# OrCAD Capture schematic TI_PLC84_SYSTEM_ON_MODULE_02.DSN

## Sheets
1 Title / Notes
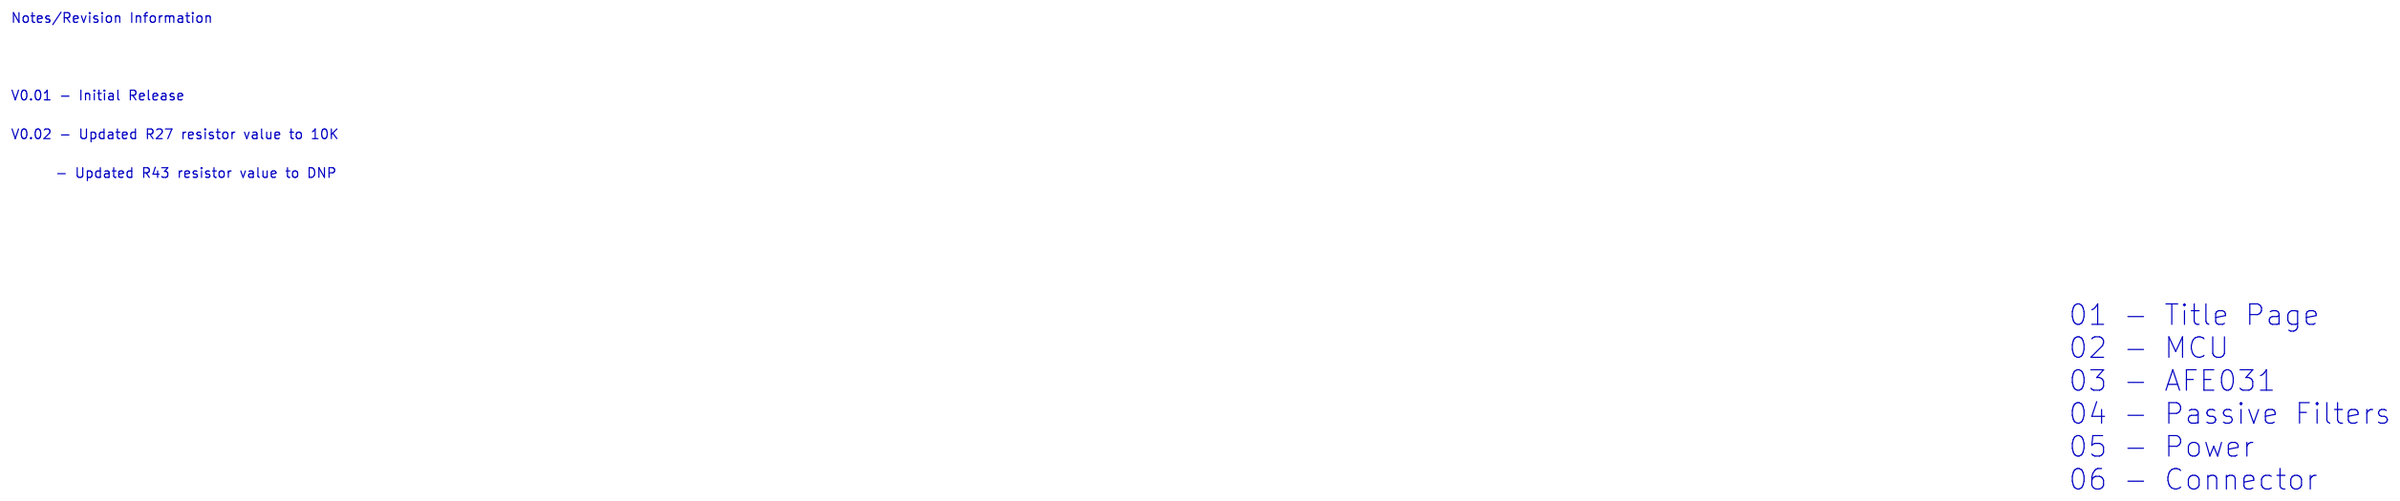
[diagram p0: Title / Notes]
2 MCU: size B; title: TIDM-SOMPLC-F28PLC84 MODULE; rev: 0.18; company: TI
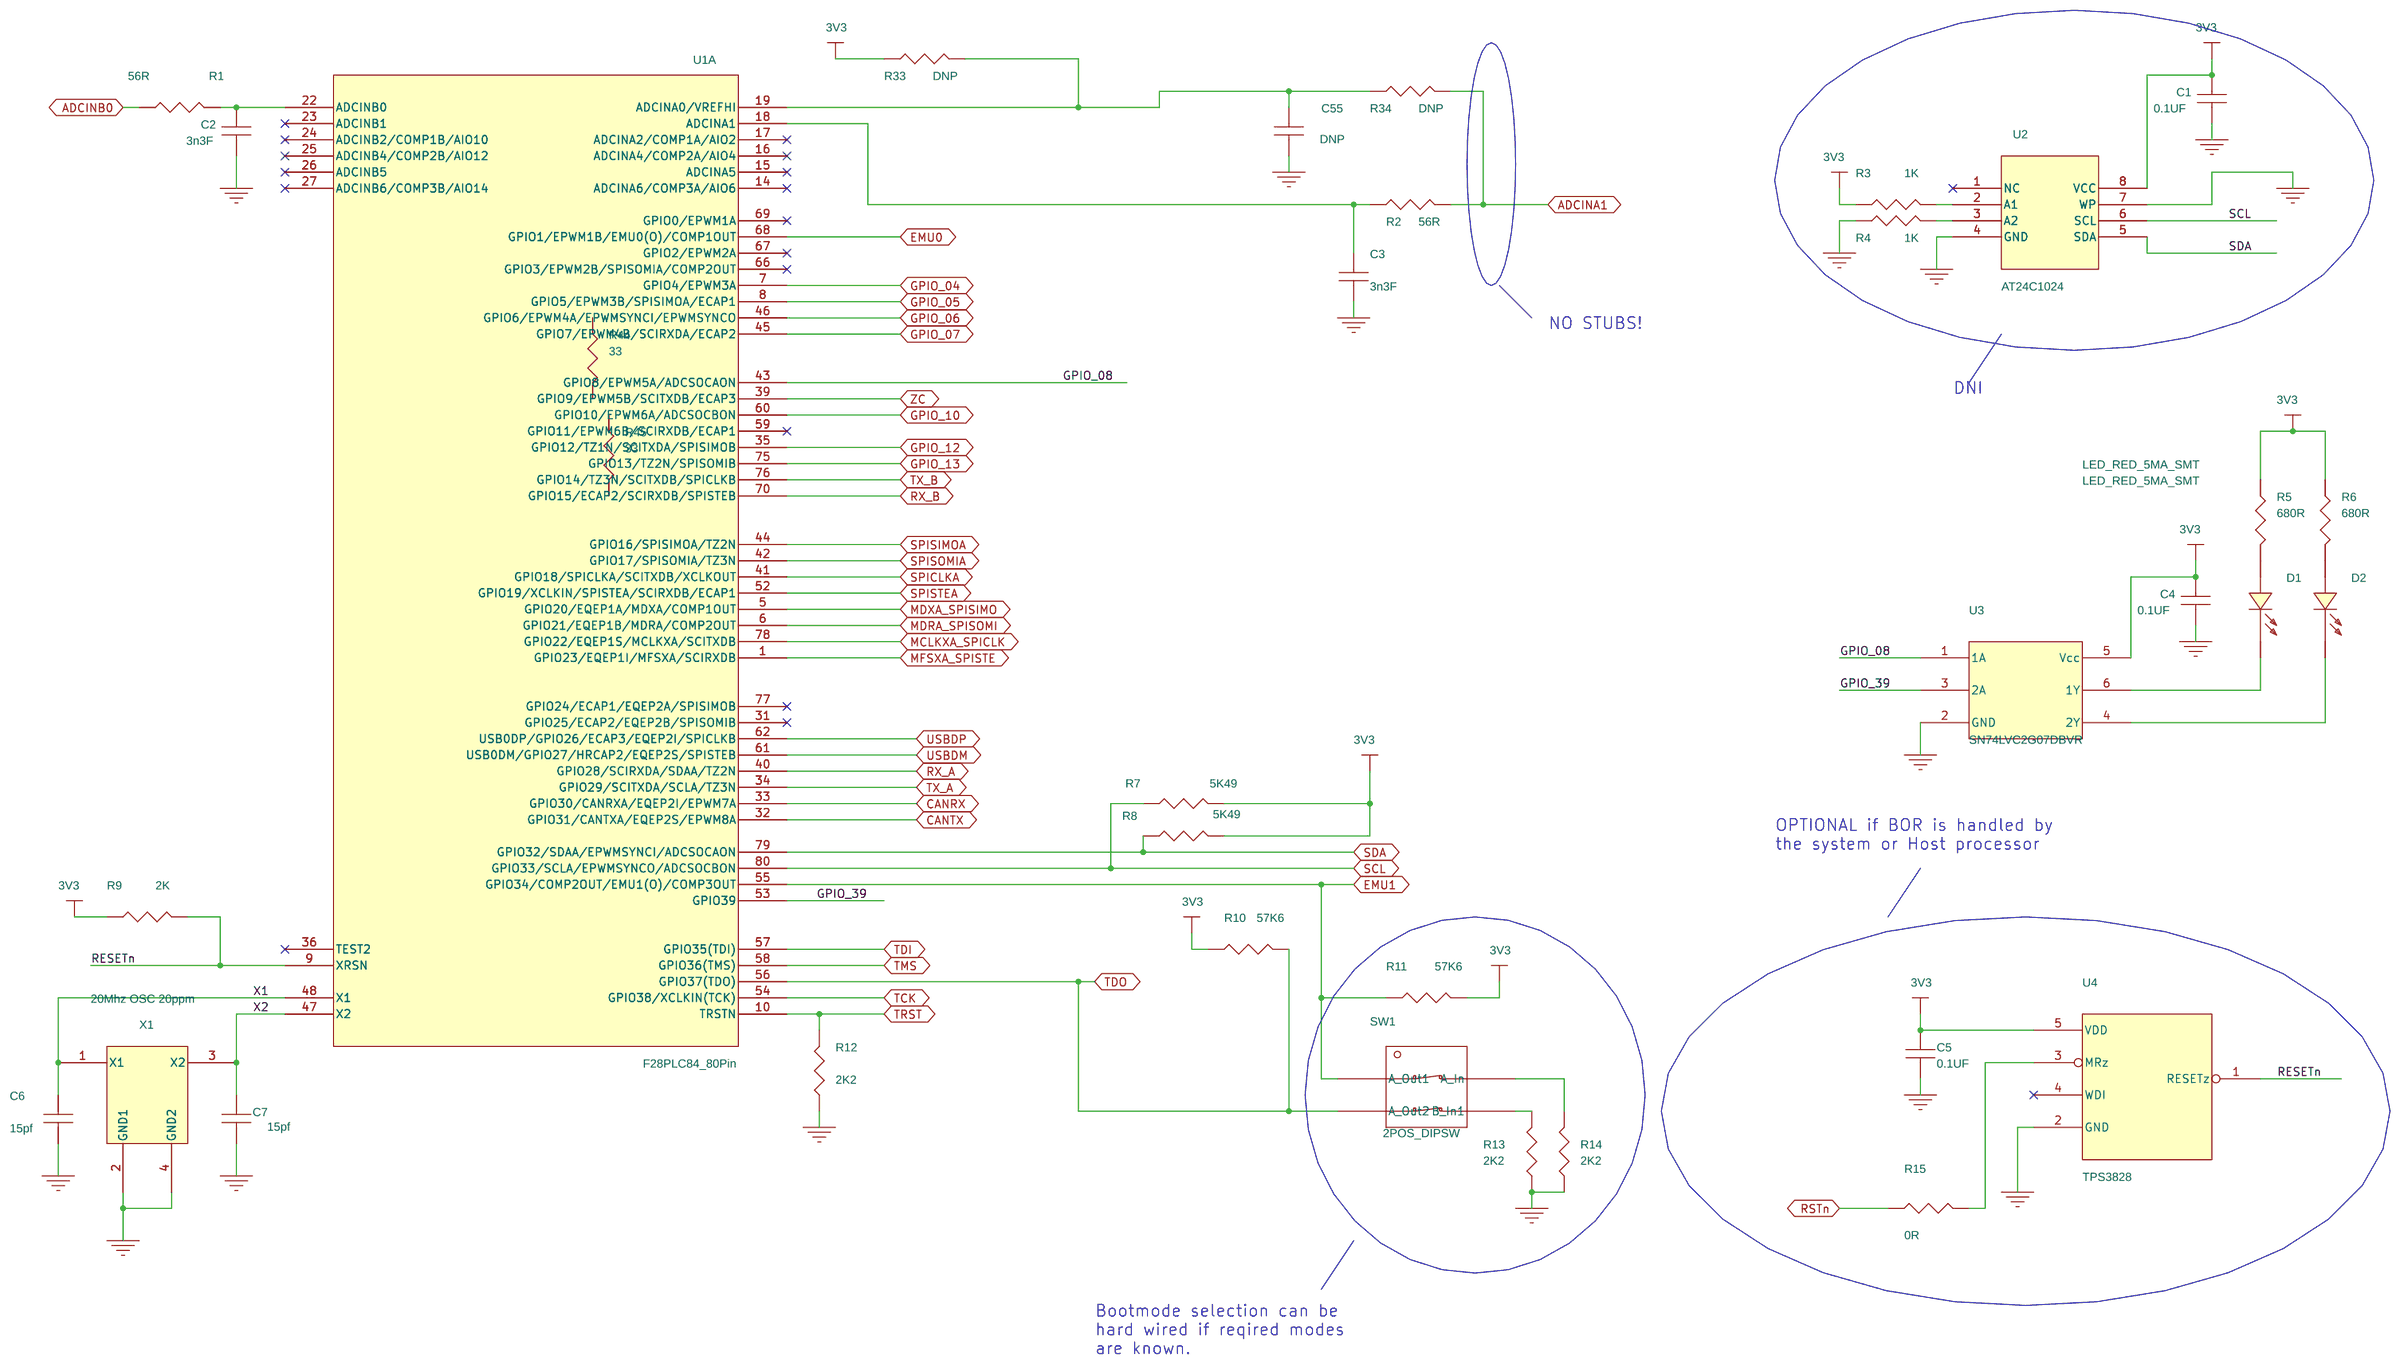
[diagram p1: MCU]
3 AFE031: size B; title: TIDM-SOMPLC-F28PLC84 MODULE; rev: 0.18; company: TI
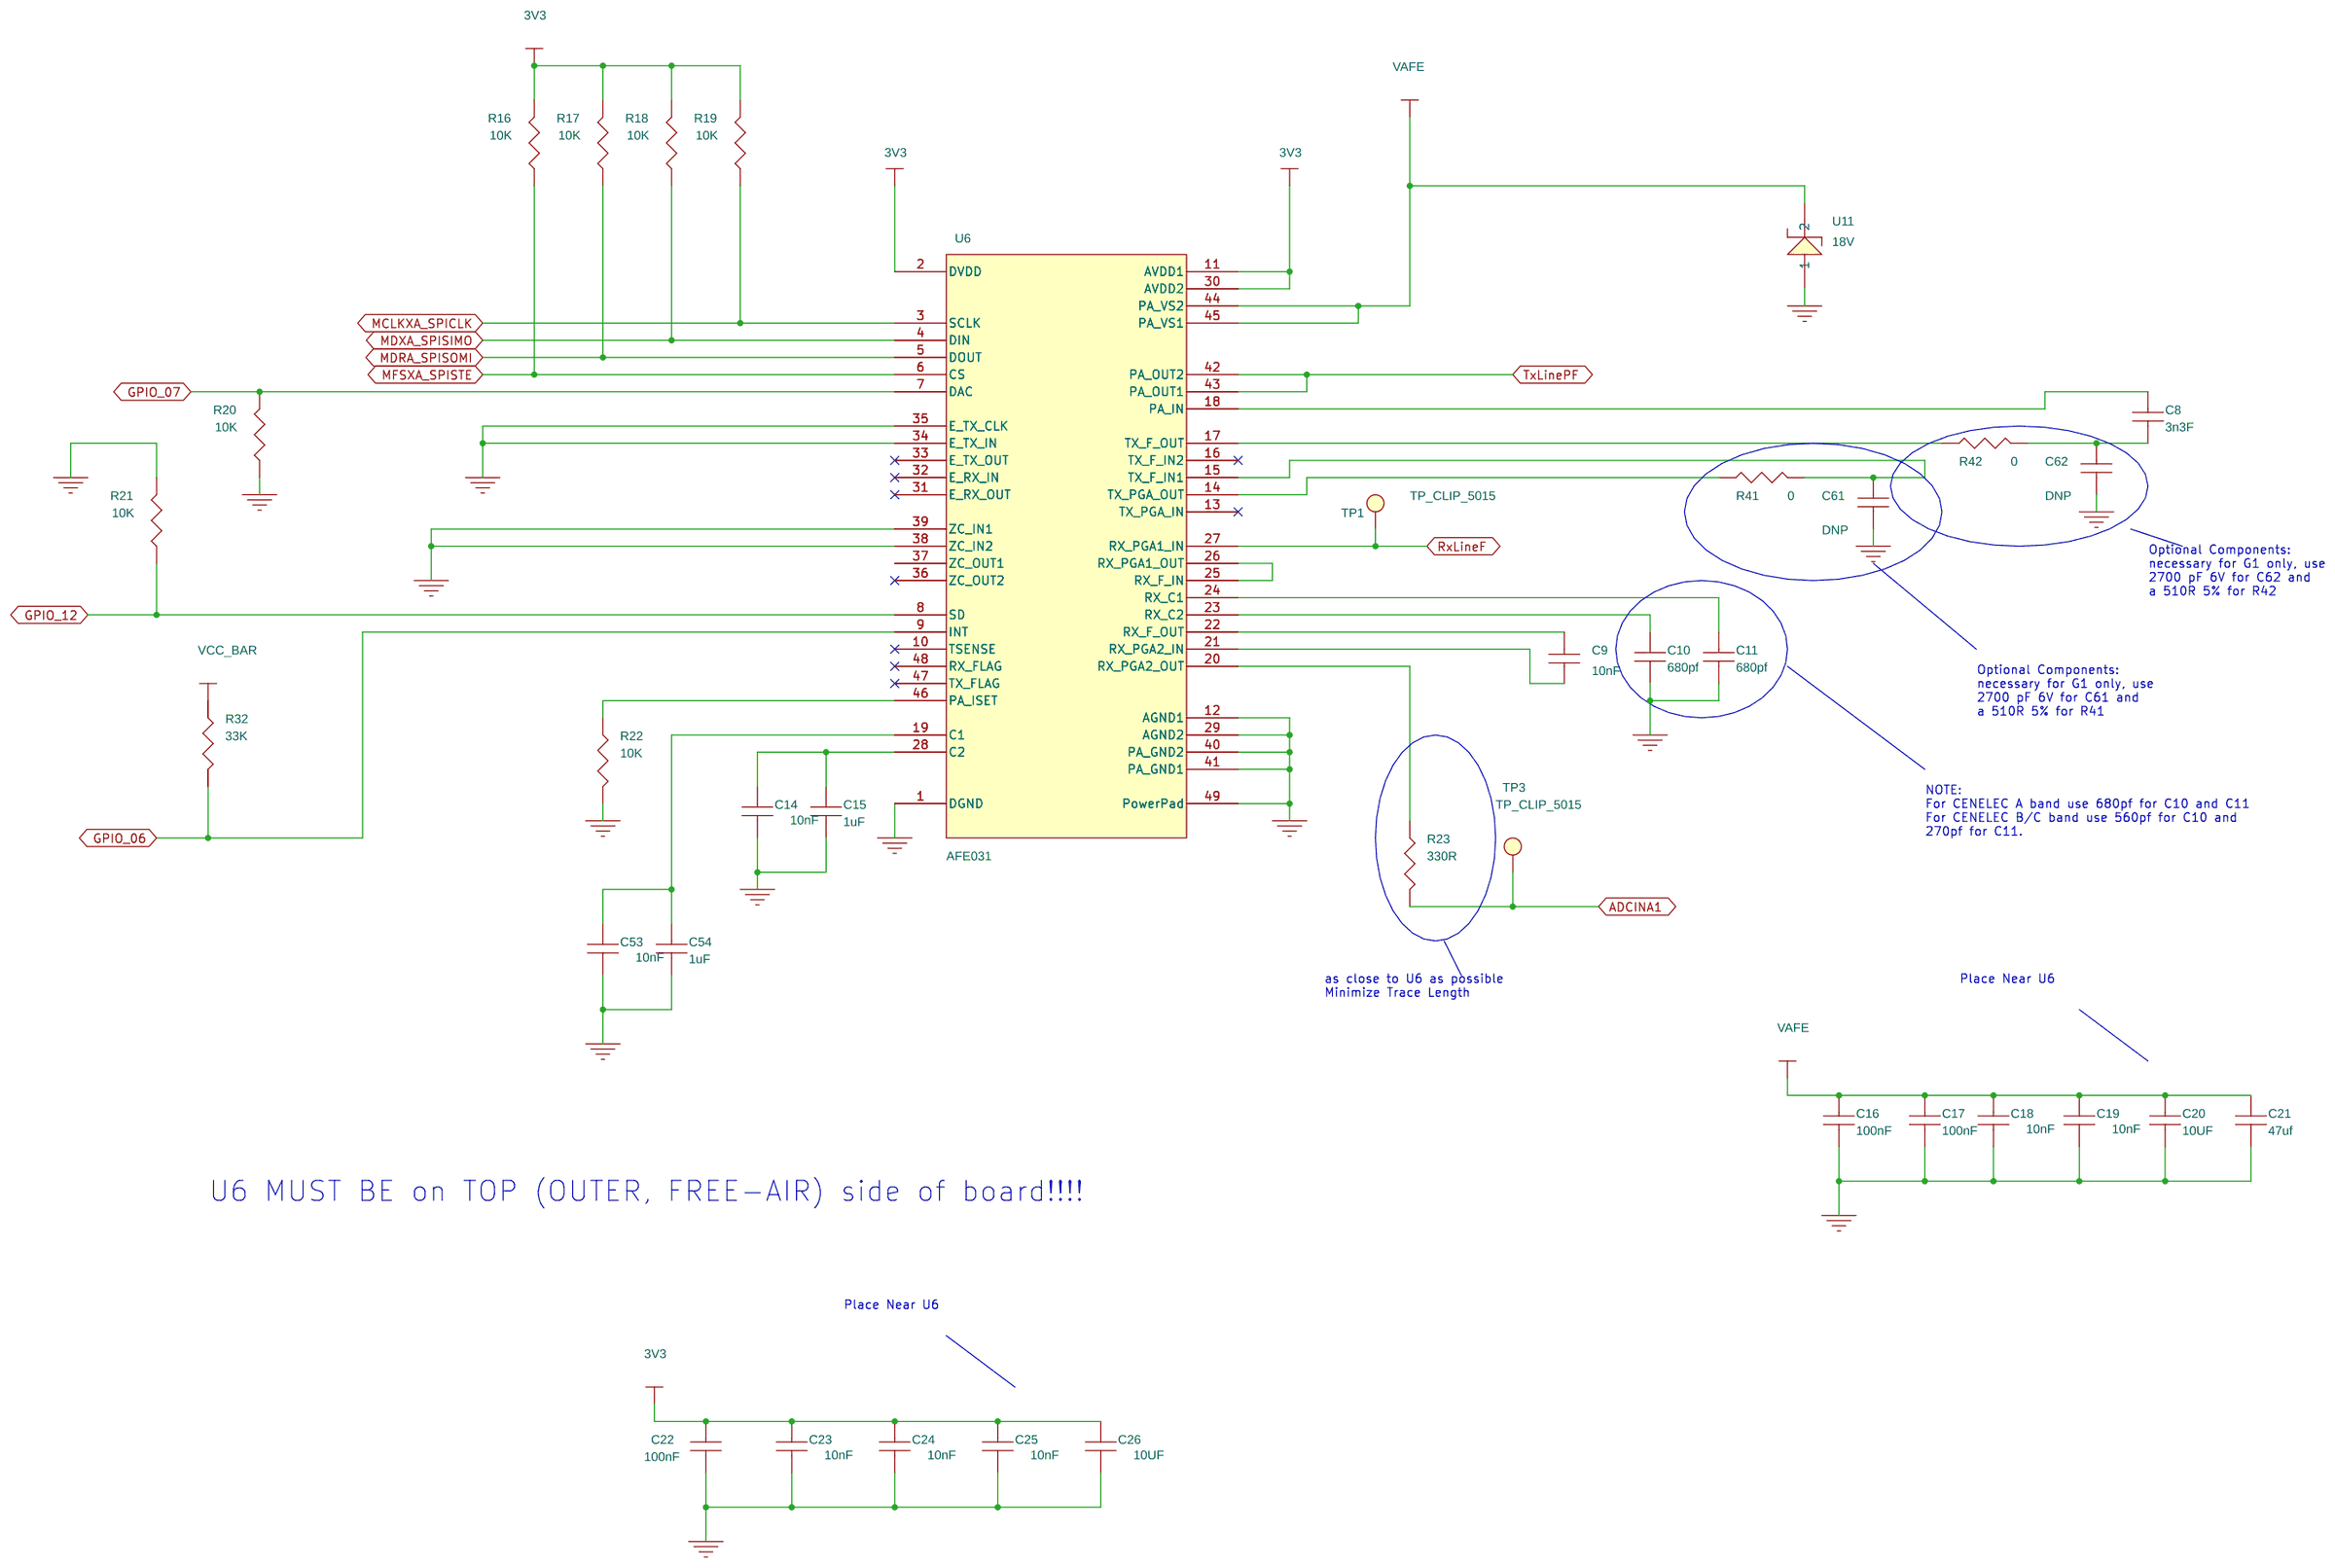
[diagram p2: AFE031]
4 Passive Filter: size B; title: TIDM-SOMPLC-F28PLC84 MODULE; rev: 0.18; company: TI
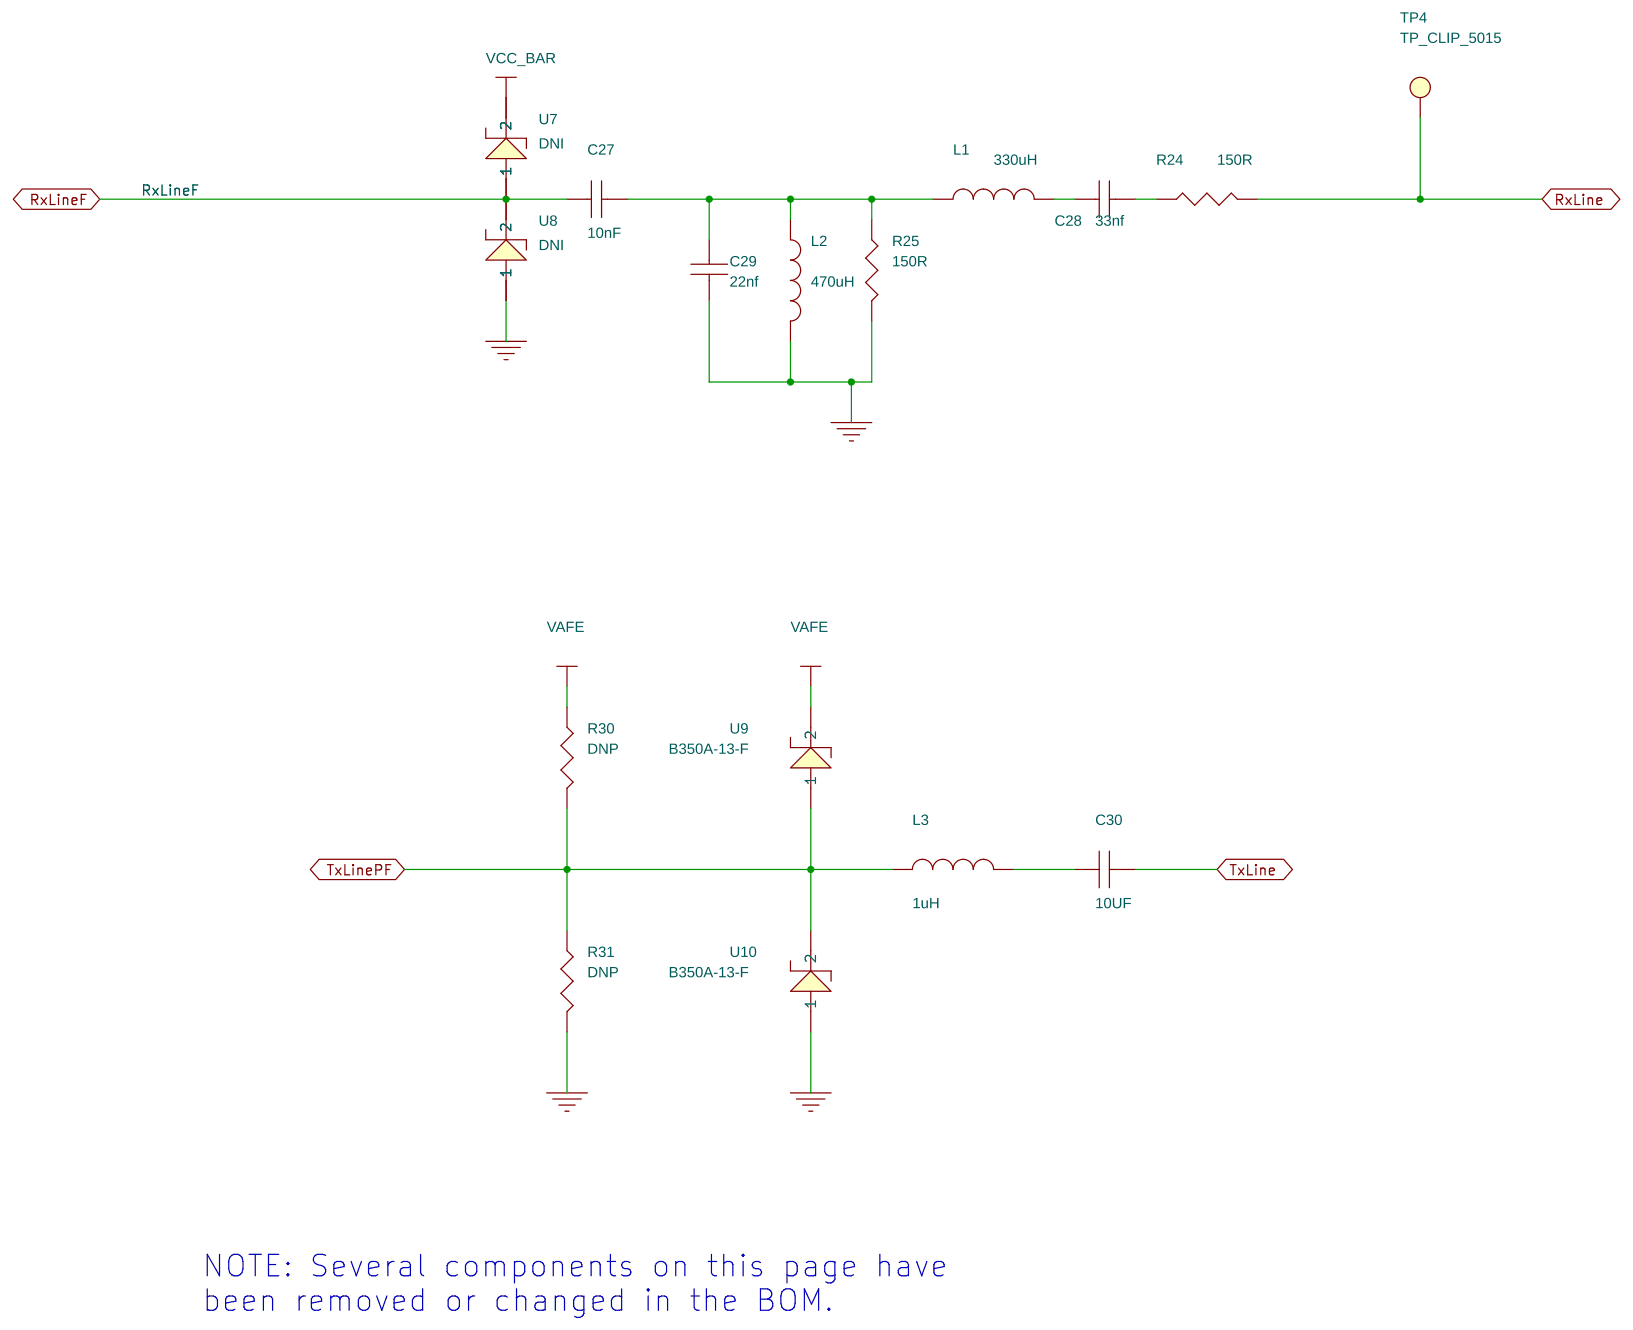
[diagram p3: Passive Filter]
5 Power: size B; title: TIDM-SOMPLC-F28PLC84 MODULE; rev: 0.18; company: TI
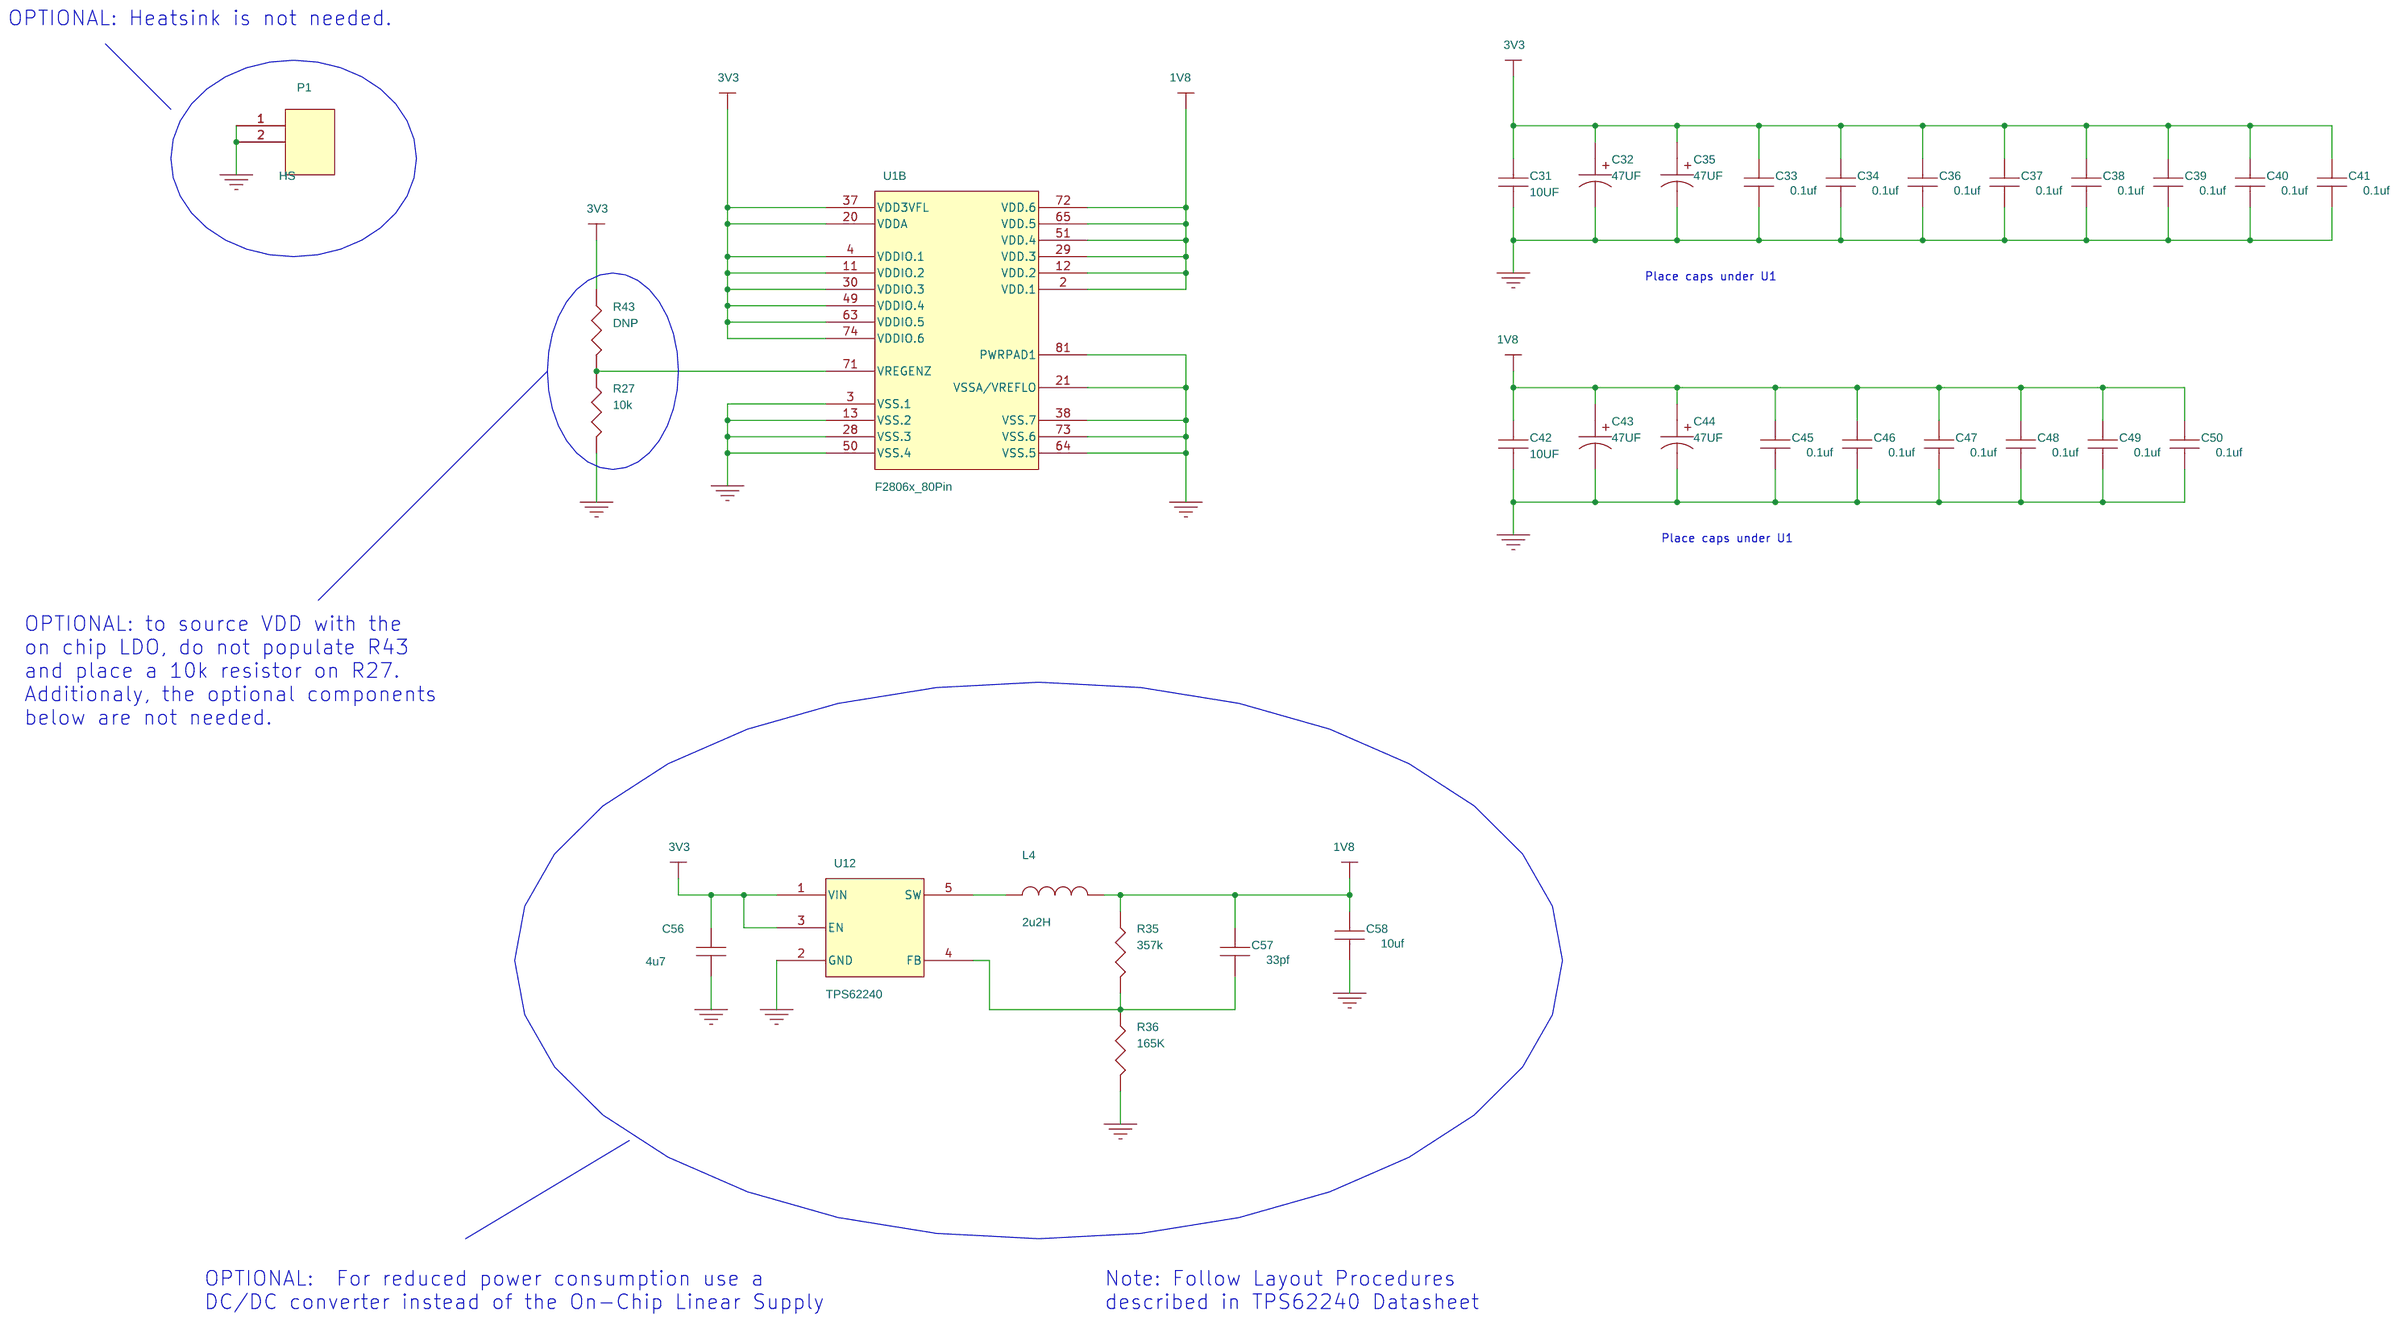
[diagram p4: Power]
6 Connector: size B; title: TIDM-SOMPLC-F28PLC84 MODULE; rev: 0.18; company: TI
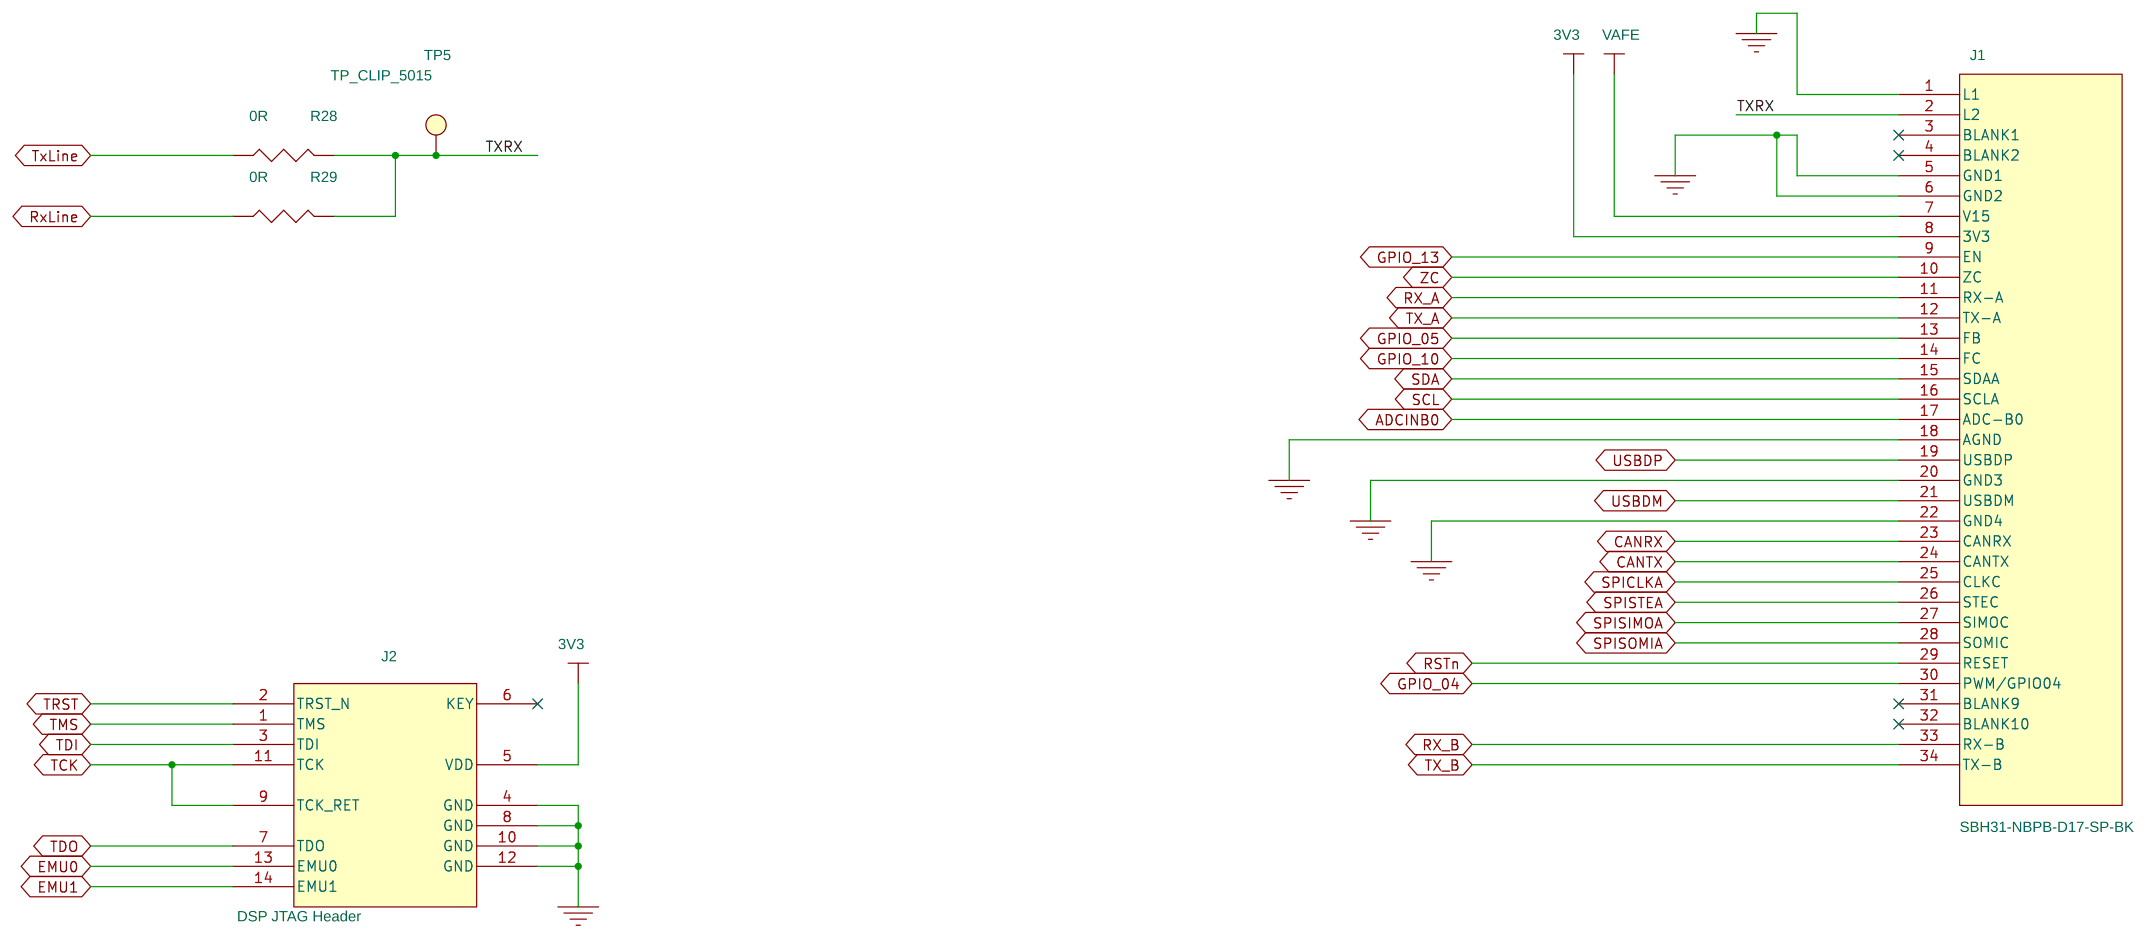
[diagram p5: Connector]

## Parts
sheet AFE031
C8  3n3F  [C1206]
C9  10nF  [C0402]
C10  680pf  [C0805]
C11  680pf  [C0805]
C14  10nF  [C0603]
C15  1uF  [C0603]
C16  100nF  [C0402]
C17  100nF  [C0402]
C18  10nF  [C0603]
C19  10nF  [C0603]
C20  10UF  [C1206]
C21  47uf  [C2220]
C22  100nF  [C0402]
C23  10nF  [C0603]
C24  10nF  [C0603]
C25  10nF  [C0603]
C26  10UF  [C0805]
C53  10nF  [C0603]
C54  1uF  [C0603]
C61  DNP  [C0402]
C62  DNP  [C0402]
R16  10K  [R0402]
R17  10K  [R0402]
R18  10K  [R0402]
R19  10K  [R0402]
R20  10K  [R0402]
R21  10K  [R0402]
R22  10K  [R0402]
R23  330R  [R0402]
R32  33K  [R0402]
R41  0  [R0402]
R42  0  [R0402]
TP1  TP_CLIP_5015  [TP_5015]
TP3  TP_CLIP_5015  [TP_5015]
U6  AFE031  [RGZ]
U11  18V  [DO-214AA]
sheet Connector
J1  SBH31-NBPB-D17-SP-BK  [male]
J2  DSP JTAG Header  [hdr_14p]
R28  0R  [R0402]
R29  0R  [R0402]
TP5  TP_CLIP_5015  [TP_5015]
sheet MCU
C1  0.1UF  [C0603]
C2  3n3F  [C0402]
C3  3n3F  [C0402]
C4  0.1UF  [C0603]
C5  0.1UF  [C0603]
C6  15pf  [C0402]
C7  15pf  [C0402]
C55  DNP  [C0402]
D1  LED_RED_5MA_SMT  [LED0603H35]
D2  LED_RED_5MA_SMT  [LED0603H35]
R1  56R  [R0402]
R2  56R  [R0402]
R3  1K  [R0402]
R4  1K  [R0402]
R5  680R  [R0603]
R6  680R  [R0603]
R7  5K49  [R0402]
R8  5K49  [R0402]
R9  2K  [R0402]
R10  57K6  [R0402]
R11  57K6  [R0402]
R12  2K2  [R0402]
R13  2K2  [R0402]
R14  2K2  [R0402]
R15  0R  [R0402]
R33  DNP  [R0402]
R34  DNP  [R0402]
R44  33  [R0805]
R45  33  [R0805]
SW1  2POS_DIPSW  [SMT218LP_2POS]
U1  F28PLC84_80Pin  [PFP (80)]  (sections A,B)
U2  AT24C1024  [TSSOP8]
U3  SN74LVC2G07DBVR  [DBV6]
U4  TPS3828  [DBV5]
X1  20Mhz OSC 20ppm  [4-SMD (0.197" L x 0.126" W)]
sheet Passive Filter
C27  10nF  [C0603]
C28  33nf  [C0402]
C29  22nf  [C0402]
C30  10UF  [C1206]
L1  330uH  [IND1210]
L2  470uH  [IND1007]
L3  1uH  [IND1207]
R24  150R  [R0402]
R25  150R  [R0402]
R30  DNP  [R0603]
R31  DNP  [R0603]
TP4  TP_CLIP_5015  [TP_5015]
U7  DNI  [DO-214AB]
U8  DNI  [DO-214AB]
U9  B350A-13-F
U10  B350A-13-F
sheet Power
C31  10UF  [C0603]
C32  47UF  [C0805P]
C33  0.1uf  [C0402]
C34  0.1uf  [C0402]
C35  47UF  [C0805P]
C36  0.1uf  [C0402]
C37  0.1uf  [C0402]
C38  0.1uf  [C0402]
C39  0.1uf  [C0402]
C40  0.1uf  [C0402]
C41  0.1uf  [C0402]
C42  10UF  [C0603]
C43  47UF  [C0805P]
C44  47UF  [C0805P]
C45  0.1uf  [C0402]
C46  0.1uf  [C0402]
C47  0.1uf  [C0402]
C48  0.1uf  [C0402]
C49  0.1uf  [C0402]
C50  0.1uf  [C0402]
C56  4u7  [C0402]
C57  33pf  [C0402]
C58  10uf  [C0603]
L4  2u2H  [IND0805]
P1  HS  [custom]
R27  10k  [R0402]
R35  357k  [R0402]
R36  165K  [R0402]
R43  DNP  [R0402]
U12  TPS62240  [DCC]

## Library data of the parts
C8 = CAP: CAP .0033UF 50V PPS FILM 1206 5%; Distributor: digikey; Distributor Part Number: PCF1334CT-ND; Part Number: 300-00038; Vendor: PANASONIC; Vendor PN: ECH-U1H332JX5; Voltage: 50V
C9 = CAP: Cap Ceramic SMT 0402; Part Number: 300-00013; Voltage: 10V
C10 C11 = CAP: CAP 680PF 50V CERAMIC X7R 0805; Distributor: digikey; Distributor Part Number: 311-1126-1-ND; Part Number: 300-00085; Vendor: yageo; Vendor PN: CC0805KRX7R9BB681; Voltage: 50V
C14 C23-C25 C53 = CAP: Part Number: 300-00040; Vendor: MURATA; Vendor PN: GRM188R71C103KA01D
C15 C54 = CAP: Cap Ceramic SMT 0603; Distributor: digikey; Distributor Part Number: 587-2400-1-ND; Part Number: 300-00036; Vendor: Taiyo Yuden; Vendor PN: UMK107BJ105KA-T; Voltage: 50V
C16 C17 = CAP: Part Number: 300-00041; Vendor: MURATA; Vendor PN: GRM155F51E104ZA01D
C18 C19 = CAP: Part Number: 300-00043; Vendor: MURATA; Vendor PN: GRM188R71E103KA01D
C20 C30 = CAP: Part Number: 300-00039; Vendor: Taiyo Yuden; Vendor PN: GMK316F106ZL-T
C21 = CAP: Part Number: 300-00042; Vendor: TDK; Vendor PN: C5750Y5V1E476Z
C22 = CAP: Cap Ceramic SMT 0402; Part Number: 300-00014; Voltage: 10V
C26 = CAP: Part Number: 300-00008; Vendor: PANASONIC; Vendor PN: ECJ-2FB0J106M
C55 C61 C62 = CAP: Cap Ceramic SMT 0402; Part Number: 300-00057
R16 = RES_10: Resistor 10K 5% - SMD,0402; Part Number: 310-00049; Part Type: RES
R17 = RES_2: Resistor 10K 5% - SMD,0402; Part Number: 310-00049; Part Type: RES
R18 = RES: Resistor 10K 5% - SMD,0402; Part Number: 310-00049
R19 = RES_4: Resistor 10K 5% - SMD,0402; Part Number: 310-00049; Part Type: RES
R20 = RES_7: Resistor 10K 5% - SMD,0402; Part Number: 310-00049; Part Type: RES
R21 = RES_8: Resistor 10K 5% - SMD,0402; Part Number: 310-00049; Part Type: RES
R22 = RES_3: Resistor 10K 5% - SMD,0402; Part Number: 310-00049; Part Type: RES
R23 = RES_5: RES 330 OHM 1/16W 5% 0402 SMD; Distributor: digikey; Distributor Part Number: 541-330JCT-ND; Part Number: 310-00063; Part Type: RES; Vendor: vishay; Vendor PN: CRCW0402330RJNED
R32 = RES_1: Part Number: 310-00067; Part Type: RES
R41 = RES_9: RES 0.0 OHM 1/10W 0402 SMD; Distributor: digikey; Distributor Part Number: P0.0JCT-ND; Part Number: 310-00102; Part Type: RES; Vendor: Panasonic - ECG; Vendor PN: ERJ-2GE0R00X
R42 = RES_6: RES 0.0 OHM 1/10W 0402 SMD; Distributor: digikey; Distributor Part Number: P0.0JCT-ND; Part Number: 310-00102; Part Type: RES; Vendor: Panasonic - ECG; Vendor PN: ERJ-2GE0R00X
TP1 TP3-TP5 = TP_CLIP: PC TEST POINT MINIATURE SMT; Part Number: 280-00005; Part Type: MTG_HOLE_TP; Vendor: TI; Datasheet: http://www.keyelco.com/products/specs/spec130.asp
U6 = AFE031: AFE031 TI PLC Integrated AFE, 48 pin QFN RGZ; Part Number: 402-00028; Part Type: IC; Vendor: TI
U11 = Diode_Zener: Part Number: 400-00007; Part Type: FET_DIODE; Vendor: On Semi; Vendor PN: 1SMB5931BT3
J1 = PlcConnector: Part Number: 320-00013; Part Type: CONN; Vendor: Sullins Connector Solutions
J2 = CONN_DSP_JTAG: CONN. 2X7 HEADER, SMT, DSP JTAG, Pin 6 removed; Part Number: 120-00068; Part Type: CONN; Vendor: SAMTEC; Vendor PN: TSM-107-01-S-DV
R28 = RES_1: Resistors, 0R, 5% - SMD, 0402; Part Number: 310-00029; Part Type: RES
R29 = RES: Resistors, 0R, 5% - SMD, 0402; Part Number: 310-00029
C1 C4 C5 = CAP: Capacitor,0.1UF,16 V,10 %,X7R,0603; Part Number: 100-00003; Tolerance: 10%; Vendor: AVX; Vendor PN: 0603YC104KAT*A; Voltage: 16V; Datasheet: http://www.avxcorp.com/docs/Catalogs/cx7r.pdf
C2 C3 = CAP: Cap Ceramic SMT 0402; Part Number: 300-00017; Voltage: 10V
C6 C7 = CAP: Part Number: 300-00056; Vendor: MURATA; Vendor PN: GRM1555C1H150JZ01D
D1 D2 = LED_SMT_RED_5MA: LED, RED, 3.0 VR, 0.2 IF,SURF. MOUNT; Part Number: 200-00010; Part Type: FET_DIODE; Vendor: PANASONIC; Vendor PN: LNJ208R8ARA; Datasheet: http://www.semicon.panasonic.co.jp/ds/eng/SHD00192AEK.pdf
R1 = RES_2: Resistors 56R, 5% - SMD, 0402; Part Number: 310-00041; Part Type: RES
R2 = RES_13: Resistors 56R, 5% - SMD, 0402; Part Number: 310-00041; Part Type: RES
R3 = RES_5: Resistors,1K,5%, SMD,0402; Part Number: 310-00035; Part Type: RES
R4 = RES_16: Resistors,1K,5%, SMD,0402; Part Number: 310-00035; Part Type: RES
R5 = RES: Resistors, 680R, 5% - SMD, 0603; Part Number: 310-00011; Tolerance: 0.05
R6 = RES_11: Resistors, 680R, 5% - SMD, 0603; Part Number: 310-00011; Part Type: RES; Tolerance: 0.05
R7 = RES_8: Resistors 5K49 5% - SMD, 0402; Part Number: 310-00042; Part Type: RES
R8 = RES_17: Resistors 5K49 5% - SMD, 0402; Part Number: 310-00042; Part Type: RES
R9 = RES_4: Resistors 2K 5% - SMD, 0402; Part Number: 310-00043; Part Type: RES
R10 = RES_7: Resistors 57K6 5% - SMD, 0402; Part Number: 310-00044; Part Type: RES
R11 = RES_18: Resistors 57K6 5% - SMD, 0402; Part Number: 310-00044; Part Type: RES
R12 = RES_9: Resistors 2K2 5% - SMD, 0402; Part Number: 310-00045; Part Type: RES
R13 = RES_15: Resistors 2K2 5% - SMD, 0402; Part Number: 310-00045; Part Type: RES
R14 = RES_1: Resistors 2K2 5% - SMD, 0402; Part Number: 310-00045; Part Type: RES
R15 = RES_10: Resistors, 0R, 5% - SMD, 0402; Part Number: 310-00029; Part Type: RES
R33 = RES_12: Resistors, DNP - SMD, 0402 (do not populate); Part Number: 310-00030; Part Type: RES
R34 = RES_3: Resistors, DNP - SMD, 0402 (do not populate); Part Number: 310-00030; Part Type: RES
R44 = RES_6: RESISTOR,33R,0.125 W,5 %,0805; Part Number: 110-00007; Part Type: RES; Tolerance: 0.05; Vendor: AVX; Vendor PN: CR21-330J-*; Voltage: 0.125W; Datasheet: http://www.avxcorp.com/docs/Catalogs/cr-cj.pdf
R45 = RES_14: RESISTOR,33R,0.125 W,5 %,0805; Part Number: 110-00007; Part Type: RES; Tolerance: 0.05; Vendor: AVX; Vendor PN: CR21-330J-*; Voltage: 0.125W; Datasheet: http://www.avxcorp.com/docs/Catalogs/cr-cj.pdf
SW1 = Switch_CT2182LPST: SWITCH DIP HALF PITCH 2POS; Distributor: Digikey; Distributor Part Number: CT2182LPST-ND; Part Number: 206-00010; Part Type: SWITCH; Vendor: CTS; Vendor PN: 218-2LPST; Datasheet: http://www.ctscorp.com/components/Datasheets/218.pdf
U1 = F2806x_80Pin: Part Number: 402-00034; Part Type: IC; Vendor: TI; Vendor PN: F28PLC84
U2 = I2C_ROM_2_ADDR: IC EEPROM 1MBIT 1MHZ 8TSSOP; Part Number: 402-00027; Part Type: IC; Vendor: Atmel; Vendor PN: AT24C1024B-TH-T; Datasheet: http://www.atmel.com/dyn/resources/prod_documents/doc1471.pdf
U3 = SN74LVC2G07DBV: IC,Dual Buffer/Driver With Open-Drain Outputs, SOT23-6; Distributor: Digikey; Distributor Part Number: 296-13494-2; Part Number: 402-00005; Part Type: IC; Vendor: TI; Datasheet: http://focus.ti.com/docs/prod/folders/print/sn74lvc2g07.html
U4 = TPS38xx: Reset Supervisor, SOT23-5; Distributor: Digikey; Distributor Part Number: 296-2638-1; Part Number: 203-00037; Part Type: POWER; Vendor: TI; Vendor PN: TPS3828-33DBV; Datasheet: http://focus.ti.com/docs/prod/folders/print/tps3828.html
X1 = Crystal_4pin_SMT: Part Number: 405-00009; Part Type: OSC_XTAL; Vendor: Abracon Corporation; Vendor PN: ABM3B-20.000MHZ-10-1-U-T
C27 = CAP: Part Number: 300-00037; Vendor: AVX; Vendor PN: 06035C103KAT2A
C28 = CAP: Cap Ceramic SMT 0402; Part Number: 300-00028
C29 = CAP: Cap Ceramic SMT 0402; Part Number: 300-00026
L1 = INDUCTOR_AIR_CORE: INDUCTOR 330UH 10% 1210 SMD; Distributor: Digikey; Distributor Part Number: PCD1432CT; Part Number: 330-00009; Part Type: MAGNETICS; Vendor: Panasonic - ECG; Vendor PN: ELJ-EA331KF
L2 = INDUCTOR_AIR_CORE_2: INDUCTOR POWER 470UH 1007; Distributor: Digikey; Distributor Part Number: 587-2194-1-ND; Part Number: 330-00010; Part Type: MAGNETICS; Vendor: Taiyo Yuden; Vendor PN: CB2518T471K
L3 = INDUCTOR_AIR_CORE_1: INDUCTOR 1.0UH 1.075A 20% SMD; Distributor: Digikey; Distributor Part Number: 587-2032-1-ND; Part Number: 330-00011; Part Type: MAGNETICS; Vendor: Taiyo Yuden; Vendor PN: LB3218T1R0M
R24 = RES: Resistor 150R 5% - SMD,0402; Part Number: 310-00051
R25 = RES_2: Resistor 150R 5% - SMD,0402; Part Number: 310-00051; Part Type: RES
R30 = RES_1: Resistors DNP - SMD, 0603 (Do NOT populate); Part Number: 110-00230; Part Type: RES
R31 = RES_3: Resistors DNP - SMD, 0603 (Do NOT populate); Part Number: 110-00230; Part Type: RES
U7 = Diode_Zener: Do Not Install; Part Number: 400-00027; Part Type: FET_DIODE; Vendor: Diodes Inc
U8 = Diode_Zener_2: Do Not Install; Part Number: 400-00027; Part Type: FET_DIODE; Vendor: Diodes Inc
U9 = Diode_Zener_1: DIODE SCHOTTKY 3A 50V SMA; Part Number: 400-00003; Part Type: FET_DIODE; Vendor: Diodes Inc
U10 = Diode_Zener_3: DIODE SCHOTTKY 3A 50V SMA; Part Number: 400-00003; Part Type: FET_DIODE; Vendor: Diodes Inc
C31 C42 = CAP: CAP CERAMIC 10UF 6.3V X5R 0603; Distributor: Digikey; Distributor Part Number: rPCC2395CT-ND; Part Number: 300-00011; Tolerance: 20%; Vendor: PANASONIC; Vendor PN: ECJ-1VB0J106M; Voltage: 10V
C32 C35 C43 C44 = CAP_POL: CAP TANT 47UF 10V 20% 0805; Distributor: Digikey; Distributor Part Number: 718-1608-1-ND; Part Number: 300-00012; Part Type: CAP; Vendor: Vishay; Vendor PN: 298D476X0010P2T; Voltage: 10V
C33 C34 C36-C41 C45-C50 = CAP: Part Number: 300-00044; Vendor: MURATA; Vendor PN: GRM155R61A104KA01D
C56 = CAP: Part Number: 300-00063; Vendor: TDK; Vendor PN: C1005X5R0G475K
C57 = CAP: Part Number: 300-00062; Vendor: Johanson Dielectrics Inc; Vendor PN: 250R07S330JV4T
C58 = CAP: Part Number: 300-00064; Vendor: TDK; Vendor PN: C1608X5R0J106M
L4 = INDUCTOR_AIR_CORE: Part Number: 330-00021; Part Type: MAGNETICS; Vendor: TDK; Vendor PN: GLCR2012T2R2M-HC
P1 = HDR_1X2: Part Number: 490-00002; Part Type: Heat_Sink
R27 = RES: RES 10K OHM 1/10W 5% 0402 SMD; Distributor: digikey; Distributor Part Number: P10KJTR-ND; Part Number: 310-00104; Vendor: Panasonic; Vendor PN: ERJ-2GEJ103X
R35 = RES_3: Part Number: 310-00090; Part Type: RES; Vendor: Panasonic; Vendor PN: ERJ-2RKF3573X
R36 = RES_2: Part Number: 310-00091; Part Type: RES; Vendor: Panasonic; Vendor PN: ERJ-2RKF1653X
R43 = RES_1: Resistors, DNP - SMD, 0402 (do not populate); Part Number: 310-00030; Part Type: RES
U12 = TPS622xx: 2.25 MHz 300 mA Step Down Converter; CrossRef: 402-00036; Part Number: 402-00037; Part Type: IC; Vendor: TI; Datasheet: www.ti.com

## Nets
1V8: C42.1 C43.1 C44.1 C45.1 C46.1 C47.1 C48.1 C49.1 C50.1 C57.1 C58.1 L4.2 R35.1 U1.2(VDD.1) U1.12(VDD.2) U1.29(VDD.3) U1.51(VDD.4) U1.65(VDD.5) U1.72(VDD.6)
3V3: C1.1 C4.1 C5.1 C22.1 C23.1 C24.1 C25.1 C26.1 C31.1 C32.1 C33.1 C34.1 C35.1 C36.1 C37.1 C38.1 C39.1 C40.1 C41.1 C56.1 J1.8(3V3) J2.5(VDD) R3.1 R5.1 R6.1 R7.2 R8.2 R9.1 R10.2 R11.2 R16.1 R17.1 R18.1 R19.1 R32.1 R33.1 R43.1 U1.4(VDDIO.1) U1.11(VDDIO.2) U1.20(VDDA) U1.30(VDDIO.3) U1.37(VDD3VFL) U1.49(VDDIO.4) U1.63(VDDIO.5) U1.74(VDDIO.6) U2.8(VCC) U3.5(Vcc) U4.5(VDD) U6.2(DVDD) U6.11(AVDD1) U6.30(AVDD2) U7.2 U12.1(VIN) U12.3(EN)
GND: C1.2 C2.2 C3.2 C4.2 C5.2 C6.2 C7.2 C10.2 C11.2 C14.2 C15.2 C16.2 C17.2 C18.2 C19.2 C20.2 C21.2 C22.2 C23.2 C24.2 C25.2 C26.2 C29.2 C31.2 C32.2 C33.2 C34.2 C35.2 C36.2 C37.2 C38.2 C39.2 C40.2 C41.2 C42.2 C43.2 C44.2 C45.2 C46.2 C47.2 C48.2 C49.2 C50.2 C53.2 C54.2 C55.2 C56.2 C58.2 C61.2 C62.2 J1.1(L1) J1.5(GND1) J1.6(GND2) J1.18(AGND) J1.20(GND3) J1.22(GND4) J2.4(GND) J2.8(GND) J2.10(GND) J2.12(GND) L2.2 P1.1 P1.2 R4.1 R12.1 R13.1 R14.1 R20.2 R21.1 R22.2 R25.2 R27.2 R31.2 R36.2 U1.3(VSS.1) U1.13(VSS.2) U1.21(VSSA/VREFLO) U1.28(VSS.3) U1.38(VSS.7) U1.50(VSS.4) U1.64(VSS.5) U1.73(VSS.6) U1.81(PWRPAD1) U2.4(GND) U2.7(WP) U3.2(GND) U4.2(GND) U6.1(DGND) U6.12(AGND1) U6.29(AGND2) U6.34(E_TX_IN) U6.35(E_TX_CLK) U6.38(ZC_IN2) U6.39(ZC_IN1) U6.40(PA_GND2) U6.41(PA_GND1) U6.49(PowerPad) U8.1 U10.1 U11.1 U12.2(GND) X1.2(GND1) X1.4(GND2)
ADCINA1: R2.2 R23.2 R34.2 TP3.1(TP1)
ADCINB0: J1.17(ADC-B0) R1.2
CANRX: J1.23(CANRX) U1.33(GPIO30/CANRXA/EQEP2I/EPWM7A)
CANTX: J1.24(CANTX) U1.32(GPIO31/CANTXA/EQEP2S/EPWM8A)
EMU0: J2.13(EMU0) U1.68(GPIO1/EPWM1B/EMU0(O)/COMP1OUT)
EMU1: J2.14(EMU1) R11.1 SW1.1(A_Out1) U1.55(GPIO34/COMP2OUT/EMU1(O)/COMP3OUT)
GPIO_04: J1.30(PWM/GPIO04) U1.7(GPIO4/EPWM3A)
GPIO_05: J1.13(FB) U1.8(GPIO5/EPWM3B/SPISIMOA/ECAP1)
GPIO_06: R32.2 U1.46(GPIO6/EPWM4A/EPWMSYNCI/EPWMSYNCO) U6.9(INT)
GPIO_07: R20.1 U1.45(GPIO7/EPWM4B/SCIRXDA/ECAP2) U6.7(DAC)
GPIO_08: U1.43(GPIO8/EPWM5A/ADCSOCAON) U3.1(1A)
GPIO_10: J1.14(FC) U1.60(GPIO10/EPWM6A/ADCSOCBON)
GPIO_12: R21.2 U1.35(GPIO12/TZ1N/SCITXDA/SPISIMOB) U6.8(SD)
GPIO_13: J1.9(EN) U1.75(GPIO13/TZ2N/SPISOMIB)
GPIO_39: U1.53(GPIO39) U3.3(2A)
MCLKXA_SPICLK: R19.2 U1.78(GPIO22/EQEP1S/MCLKXA/SCITXDB) U6.3(SCLK)
MDRA_SPISOMI: R17.2 U1.6(GPIO21/EQEP1B/MDRA/COMP2OUT) U6.5(DOUT)
MDXA_SPISIMO: R18.2 U1.5(GPIO20/EQEP1A/MDXA/COMP1OUT) U6.4(DIN)
MFSXA_SPISTE: R16.2 U1.1(GPIO23/EQEP1I/MFSXA/SCIRXDB) U6.6(CS)
RESETn: R9.2 U1.9(XRSN) U4.1(RESETz)
RSTn: J1.29(RESET) R15.1
RX_A: J1.11(RX-A) U1.40(GPIO28/SCIRXDA/SDAA/TZ2N)
RX_B: J1.33(RX-B) U1.70(GPIO15/ECAP2/SCIRXDB/SPISTEB)
RxLine: R24.2 R29.2 TP4.1(TP1)
RxLineF: C27.1 TP1.1(TP1) U6.27(RX_PGA1_IN) U7.1 U8.2
SCL: J1.16(SCLA) R7.1 U1.80(GPIO33/SCLA/EPWMSYNCO/ADCSOCBON) U2.6(SCL)
SDA: J1.15(SDAA) R8.1 U1.79(GPIO32/SDAA/EPWMSYNCI/ADCSOCAON) U2.5(SDA)
SPICLKA: J1.25(CLKC) U1.41(GPIO18/SPICLKA/SCITXDB/XCLKOUT)
SPISIMOA: J1.27(SIMOC) U1.44(GPIO16/SPISIMOA/TZ2N)
SPISOMIA: J1.28(SOMIC) U1.42(GPIO17/SPISOMIA/TZ3N)
SPISTEA: J1.26(STEC) U1.52(GPIO19/XCLKIN/SPISTEA/SCIRXDB/ECAP1)
TCK: J2.9(TCK_RET) J2.11(TCK) U1.54(GPIO38/XCLKIN(TCK))
TDI: J2.3(TDI) U1.57(GPIO35(TDI))
TDO: J2.7(TDO) R10.1 SW1.3(A_Out2) U1.56(GPIO37(TDO))
TMS: J2.1(TMS) U1.58(GPIO36(TMS))
TRST: J2.2(TRST_N) R12.2 U1.10(TRSTN)
TX_A: J1.12(TX-A) U1.34(GPIO29/SCITXDA/SCLA/TZ3N)
TX_B: J1.34(TX-B) U1.76(GPIO14/TZ3N/SCITXDB/SPICLKB)
TxLine: C30.2 R28.2
TxLinePF: L3.1 R30.2 R31.1 U6.42(PA_OUT2) U6.43(PA_OUT1) U9.1 U10.2
TXRX: J1.2(L2) R28.1 R29.1 TP5.1(TP1)
USBDM: J1.21(USBDM) U1.61(USB0DM/GPIO27/HRCAP2/EQEP2S/SPISTEB)
USBDP: J1.19(USBDP) U1.62(USB0DP/GPIO26/ECAP3/EQEP2I/SPICLKB)
Vafe: C16.1 C17.1 C18.1 C19.1 C20.1 C21.1 J1.7(V15) R30.1 U6.44(PA_VS2) U6.45(PA_VS1) U9.2 U11.2
X1: C6.1 U1.48(X1) X1.1(X1)
X2: C7.1 U1.47(X2) X1.3(X2)
ZC: J1.10(ZC) U1.39(GPIO9/EPWM5B/SCITXDB/ECAP3)
N3071748: R13.2 SW1.4(B_In1)
N3074420: R14.2 SW1.2(A_In)
N3094772: C2.1 R1.1 U1.22(ADCINB0)
N16865157: R15.2 U4.3(MRz)
N16958838: C27.2 C29.1 L1.1 L2.1 R25.1
N16958924: C28.2 R24.1
N16958926: C28.1 L1.2
N16980343: R4.2 U2.3(A2)
N16980558: R3.2 U2.2(A1)
N17027444: D1.2(CATHODE) U3.6(1Y)
N17027448: D2.2(CATHODE) U3.4(2Y)
N17127534: C14.1 C15.1 U6.28(C2)
N17128593: C11.1 U6.24(RX_C1)
N17128864: C10.1 U6.23(RX_C2)
N17131129: C8.1 U6.18(PA_IN)
N17135557: C9.1 U6.21(RX_PGA2_IN)
N17135844: C9.2 U6.22(RX_F_OUT)
N17136132: U6.25(RX_F_IN) U6.26(RX_PGA1_OUT)
N17146335: R22.1 U6.46(PA_ISET)
N17204489: R23.1 U6.20(RX_PGA2_OUT)
N17288049: C30.1 L3.2
N17293558: R27.1 R43.2 U1.71(VREGENZ)
N17337643: C53.1 C54.1 U6.19(C1)
N17341552: C3.1 R2.1 U1.18(ADCINA1)
N17342030: C55.1 R33.2 R34.1 U1.19(ADCINA0/VREFHI)
N17348812: L4.1 U12.5(SW)
N17348869: C57.2 R35.2 R36.1 U12.4(FB)
N17359246: R42.1 U6.17(TX_F_OUT)
N17359793: R41.1 U6.14(TX_PGA_OUT)
N17359944: C8.2 C62.1 R42.2
N17360694: C61.1 R41.2 U6.15(TX_F_IN1)
N17419212: D1.1(ANODE) R5.2
N17419213: D2.1(ANODE) R6.2

Not connected (* = marked no-connect by the designer): J1 3(BLANK1)* 4(BLANK2)* 31(BLANK9)* 32(BLANK10)*; J2 6(KEY)*; R44 1 2; R45 1 2; U1 14(ADCINA6/COMP3A/AIO6)* 15(ADCINA5)* 16(ADCINA4/COMP2A/AIO4)* 17(ADCINA2/COMP1A/AIO2)* 23(ADCINB1)* 24(ADCINB2/COMP1B/AIO10)* 25(ADCINB4/COMP2B/AIO12)* 26(ADCINB5)* 27(ADCINB6/COMP3B/AIO14)* 31(GPIO25/ECAP2/EQEP2B/SPISOMIB)* 36(TEST2)* 59(GPIO11/EPWM6B/SCIRXDB/ECAP1)* 66(GPIO3/EPWM2B/SPISOMIA/COMP2OUT)* 67(GPIO2/EPWM2A)* 69(GPIO0/EPWM1A)* 77(GPIO24/ECAP1/EQEP2A/SPISIMOB)*; U2 1(NC)*; U4 4(WDI)*; U6 10(TSENSE)* 13(TX_PGA_IN)* 16(TX_F_IN2)* 31(E_RX_OUT)* 32(E_RX_IN)* 33(E_TX_OUT)* 36(ZC_OUT2)* 37(ZC_OUT1) 47(TX_FLAG)* 48(RX_FLAG)*

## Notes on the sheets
sheet 1
- Notes/Revision Information
- V0.01 - Initial Release
- V0.02 - Updated R27 resistor value to 10K
- - Updated R43 resistor value to DNP
- 01 - Title Page
  02 - MCU
  03 - AFE031
  04 - Passive Filters
  05 - Power
  06 - Connector
sheet 2
- NO STUBS!
- DNI
- OPTIONAL if BOR is handled by
  the system or Host processor
- Bootmode selection can be
  hard wired if reqired modes
  are known.
sheet 3
- Optional Components:
  necessary for G1 only, use
  2700 pF 6V for C62 and
  a 510R 5% for R42
- Optional Components:
  necessary for G1 only, use
  2700 pF 6V for C61 and
  a 510R 5% for R41
- NOTE:
  For CENELEC A band use 680pf for C10 and C11
  For CENELEC B/C band use 560pf for C10 and
  270pf for C11.
- as close to U6 as possible
  Minimize Trace Length
- Place Near U6
- U6 MUST BE on TOP (OUTER, FREE-AIR) side of board!!!!
- Place Near U6
sheet 4
- NOTE: Several components on this page have
  been removed or changed in the BOM.
sheet 5
- OPTIONAL: Heatsink is not needed.
- Place caps under U1
- Place caps under U1
- OPTIONAL: to source VDD with the
  on chip LDO, do not populate R43
  and place a 10k resistor on R27.
  Additionaly, the optional components
  below are not needed.
- OPTIONAL:  For reduced power consumption use a
  DC/DC converter instead of the On-Chip Linear Supply
- Note: Follow Layout Procedures
  described in TPS62240 Datasheet
